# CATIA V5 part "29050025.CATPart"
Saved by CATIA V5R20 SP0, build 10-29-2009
Part number: 29050025
Definition: NONE
Nomenclature: 29050025
Source: Unknown
Description: 29050025
Bounding box of the stored display mesh (mm): x -12.5 to 44.548, y -39 to 73.548, z -29 to 29
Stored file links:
  C:\Users\Utente\Desktop\IO LAVORO\3D X SITO CF\X SITO\PLASTICA\RF1\29050025.CATPart
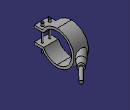
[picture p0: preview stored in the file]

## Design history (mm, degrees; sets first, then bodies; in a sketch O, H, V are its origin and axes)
Body1 "29050025" (main body)
  Solid1: solid without history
